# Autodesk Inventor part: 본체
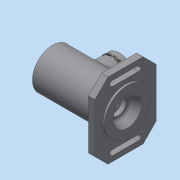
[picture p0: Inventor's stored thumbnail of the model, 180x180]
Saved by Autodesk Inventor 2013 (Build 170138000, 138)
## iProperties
Created: 2017-10
Part Number: 본체
Material: 일반
Document SubType Name: Modeling
Designer: dgall
Density: 1 g/cm^3
Author: dgall
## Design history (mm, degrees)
sketch "스케치1"
  geometry: L1 (-57.5, 0)-(57.5, 0); L2 (-57.5, 21)-(-57.5, 31); L3 (-57.5, 21)-(-48.5, 21); L4 (-48.5, 21)-(-48.5, 24); L5 (-48.5, 24)-(-45.5, 24); L6 (-45.5, 24)-(-45.5, 20); L7 (-45.5, 20)-(-36.5, 20); L8 (-36.5, 20)-(-36.5, 17.5); L9 (-36.5, 17.5)-(-33.25, 17.5); L10 (-33.25, 17.5)-(-33.25, 18.5); L11 (-33.25, 18.5)-(-31.5, 18.5); L12 (-31.5, 18.5)-(-31.5, 17.5); L13 (-31.5, 17.5)-(-20.5, 17.5); L14 (-20.5, 26)-(17.5, 26); L15 (17.5, 17.5)-(28.5, 17.5); L16 (28.5, 17.5)-(28.5, 16.5); L17 (28.5, 16.5)-(33.5, 16.5); L18 (33.5, 16.5)-(33.5, 10); L19 (33.5, 10)-(36.2, 10); L20 (36.2, 10)-(36.2, 12.5); L21 (36.2, 12.5)-(42.8, 12.5); L22 (42.8, 12.5)-(43.5, 12.904); L23 (43.5, 12.904)-(43.5, 16); L24 (43.5, 16)-(57.5, 22); L25 (-57.5, 31)-(44.5, 31); L26 (44.5, 31)-(44.5, 40); L27 (44.5, 40)-(54.5, 40); L28 (54.5, 40)-(54.5, 35); L29 (54.5, 35)-(57.5, 35); L30 (57.5, 35)-(57.5, 22); L31 (-20.5, 26)-(-20.5, 17.5); L32 (17.5, 26)-(17.5, 17.5); 3 further points
  constraints: 64 end point, 23 parallel, 6 perpendicular, 2 midpoint, 2 vertical alignment, 1 coincident, 1 horizontal
  dimensions: "d0" = 115 distance of L1.start L1.end; "d2" = 62 diameter of L25 L1; "d3" = 42 diameter of L3 L1; "d4" = 48 diameter of L5 L1; "d5" = 40 diameter of L7 L1; "d6" = 35 diameter of L9 L1; "d7" = 37 diameter of L11 L1; "d8" = 35 diameter of L13 L1; "d9" = 52 diameter of L14 L1; "d10" = 35 diameter of L15 L1; "d11" = 33 diameter of L17 L1; "d12" = 20 diameter of L18.end L1; "d13" = 25 diameter of L21 L1; "d14" = 30 deg angle of L21 L22; "d15" = 0.7 horizontal distance of L21.end L22.end; "d16" = 32 diameter of L23.end L1; "d17" = 44 diameter of L24.end L1; "d18" = 70 diameter of L29 L1; "d19" = 14 horizontal distance of L24.end L22.end; "d20" = 3 distance of L4.end L5.end; "d21" = 12 distance between parallel lines of L2 L6; "d22" = 21 horizontal distance of L2.start L7.end; "d23" = 1.75 distance of L10.end L11.end; "d24" = 26 horizontal distance of L2.start L12.end; "d25" = 38 distance of L14.start L14.end; "d26" = 60 horizontal distance of L15.end L11.end; "d29" = 7.3 horizontal distance of L19.end L22.end; "d30" = 2.7 distance of L18.end L19.end; "d31" = 3 distance of L28.end L29.end; "d32" = 10 distance of L26.end L27.end; "d33" = 80 diameter of L27 L1; "d34" = 11 distance of L12.end L13.end
revolve "회전1" sketch "스케치1" stored, may be unused: angle "d35" = 90 deg
sketch "스케치2"
  geometry: L1 (-58, 47)-(58, 47); L2 (58, 47)-(58, -47); L3 (58, -47)-(-58, -47); L4 (-58, -47)-(-58, 47); C1 r 35 at (0, 0) reference; C2 r 40 at (0, 0) reference; 2 further points
  constraints: 8 end point, 2 midpoint, 2 parallel, 1 horizontal, 1 horizontal alignment, 1 perpendicular, 1 vertical alignment
  dimensions: "d36" = 116 distance of L1.start L1.end; "d38" = 94 distance of L1.end L2.end
extrude "돌출1" join sketch "스케치2" distance "d39" = 10; taper "d40" = 0 deg
chamfer "모따기1" distance "d41" = 20; stored, may be unused: second distance "d42" = 2, angle "d43" = 45 deg
feature "스레드1" dims "d44" = 10, "d45" = 0
node "작업 평면1"
sketch "스케치3"
  geometry: L1 (57.5, 31)-(57.5, -31) reference; C1 r 25 at (1.5, 0); 1 further point
  constraints: 1 centre point, 1 horizontal alignment
  dimensions: "d47" = 50 diameter of C1; "d49" = 31 distance edge to line of C1 L1
extrude "돌출2" join sketch "스케치3" stored distance "d50" = 10; taper "d51" = 0 deg
sketch "스케치4"
  geometry: C1 r 25 at (0, 0) reference; 2 further points
  constraints: 1 coincident
hole "구멍1" sketch "스케치4" at (0, 0) diameter "d52" = 32; stored, may be unused: countersink angle "d56" = 90 deg, drill point angle "d58" = 0 deg; dims "d53" = 6, "d54" = 4, "d55" = 2, "d57" = 50
sketch "스케치5"
  geometry: C1 r 16 at (0, 0) reference; 3 further points
  constraints: 2 vertical alignment
  dimensions: "d59" = 20.5 distance of C1.centre point (0, -20.5); "d60" = 20.5 distance of point (0, 20.5) C1.centre (= d59)
hole "구멍2" sketch "스케치5" at (0, 20.5), (0, -20.5) diameter "d61" = 2.459; stored, may be unused: countersink angle "d65" = 82 deg, drill point angle "d67" = 118 deg; dims "d62" = 6, "d63" = 3.023, "d64" = 2, "d66" = 8
fillet "모깎기1" dims "d68" = 0.3
fillet "모깎기2" dims "d69" = 0.3
fillet "모깎기3" dims "d70" = 3
fillet "모깎기4" dims "d71" = 3
fillet "모깎기5" dims "d72" = 3
chamfer "모따기2" distance "d73" = 1; stored, may be unused: second distance "d74" = 2, angle "d75" = 45 deg
chamfer "모따기3" distance "d76" = 1; stored, may be unused: second distance "d77" = 2, angle "d78" = 45 deg
fillet "모깎기6" dims "d79" = 3
sketch "스케치6"
  geometry: L1 (116, 54)-(116, 0) reference; L2 (8, 47)-(8, 7); L3 (16, 7)-(16, 47); C1 r 35 at (58, 27) reference; A1 r 4 centre (12, 7) between (8, 7) and (16, 7); A2 r 4 centre (12, 47) between (16, 47) and (8, 47)
  constraints: 4 end point, 4 point on circle, 4 tangent, 2 centre point, 2 parallel
  dimensions: "d80" = 20 vertical distance of A1.centre C1.centre; "d81" = 20 vertical distance of A2.centre C1.centre; "d82" = 4 radius of A2; "d83" = 46 horizontal distance of C1.centre A2.centre
extrude "돌출3" cut sketch "스케치6" distance "d84" = 10; taper "d85" = 0 deg
node "작업 평면2"
node "작업 평면3"
sketch "스케치7"
  geometry: L1 (-56, -78)-(-56, -16) reference; L2 (-25, 0)-(25, 0) reference; 2 further points
  constraints: 1 other
  dimensions: "d87" = 56 distance from line of L1 point (0, -10); "d88" = 10 distance from line of point (0, -10) L2
node "작업 평면4"
feature "엠보싱1" dims "d89" = 0.5, "d90" = 0
node "솔리드1"
mirror "대칭1"
other parameters: "d46" = 47, "d86" = 0
